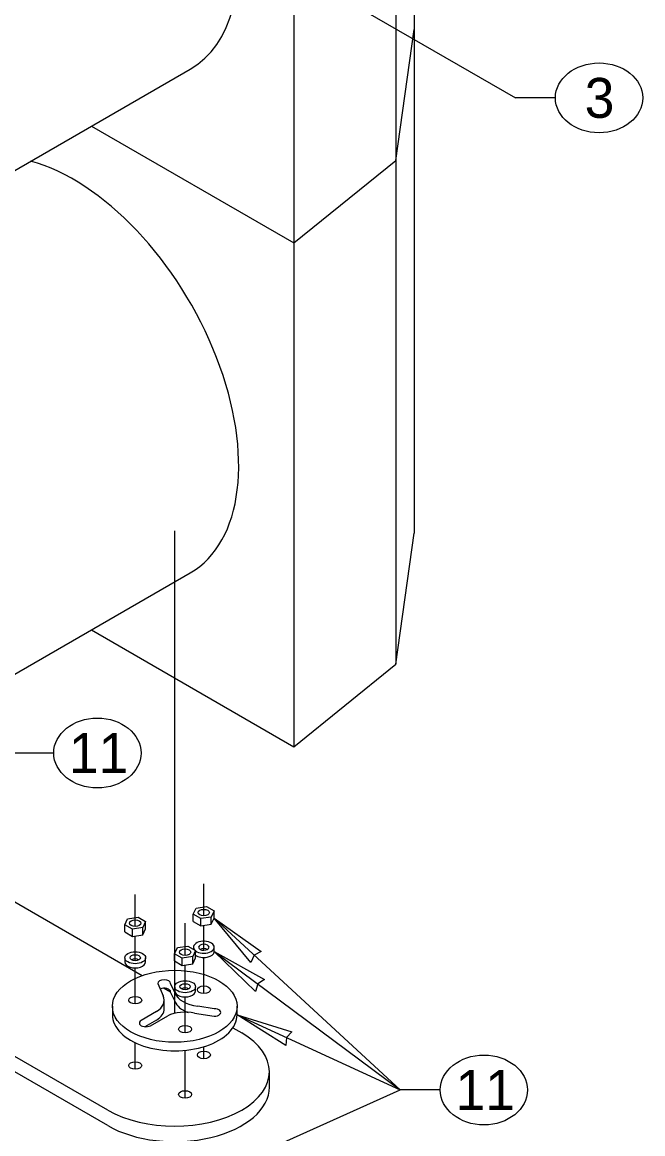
# Model space of a CAD drawing. Extents: x 99862 to 104211, y 98939 to 105076.
# Drawn here: x 101103.8 to 101352.5, y 103287.2 to 103732.8 of the extents above; entities that cross this region are included whole.
import ezdxf

# ---------------------------------------------------------------- set-up
doc = ezdxf.new("R2010")
doc.units = 0
for name, color, linetype in [('Level 11', 7, 'Continuous'), ('Level 12', 7, 'Continuous'), ('Level 15', 7, 'Continuous'), ('Level 19', 7, 'Continuous'), ('Level 20', 7, 'Continuous'), ('Level 21', 7, 'Continuous'), ('Level 26', 7, 'Continuous'), ('Level 8', 7, 'Continuous')]:
    doc.layers.add(name, color=color, linetype=linetype)

msp = doc.modelspace()

# ---------------------------------------------------------------- linework, layer by layer
at = {"layer": 'Level 11'}
for p, q in [((101172.31, 103375.22), (101173.43, 103377.64)), ((101173.43, 103377.64), (101177.61, 103378.28)), ((101177.61, 103378.28), (101180.67, 103376.52)), ((101144.87, 103371.02), (101145.99, 103373.43)), ((101145.99, 103373.43), (101150.17, 103374.08)), ((101150.17, 103374.08), (101153.23, 103372.31)), ((101172.31, 103372.31), (101172.31, 103375.22)), ((101175.37, 103373.45), (101172.31, 103375.22)), ((101179.55, 103374.1), (101175.37, 103373.45)), ((101175.37, 103370.54), (101175.37, 103373.45)), ((101180.67, 103376.52), (101179.55, 103374.1)), ((101179.55, 103371.19), (101179.55, 103374.1)), ((101179.55, 103371.19), (101180.67, 103373.61)), ((101180.67, 103373.61), (101180.67, 103376.52)), ((101144.87, 103368.11), (101144.87, 103371.02)), ((101147.93, 103369.25), (101144.87, 103371.02)), ((101144.87, 103368.11), (101147.93, 103366.34)), ((101152.11, 103369.9), (101147.93, 103369.25)), ((101147.93, 103366.34), (101147.93, 103369.25)), ((101153.23, 103372.31), (101152.11, 103369.9)), ((101152.11, 103366.99), (101152.11, 103369.9)), ((101152.11, 103366.99), (101153.23, 103369.4)), ((101153.23, 103369.4), (101153.23, 103372.31)), ((101172.31, 103372.31), (101175.37, 103370.54)), ((101175.37, 103370.54), (101179.55, 103371.19)), ((101147.93, 103366.34), (101152.11, 103366.99)), ((101164.86, 103359.4), (101165.98, 103361.82)), ((101164.86, 103356.5), (101164.86, 103359.4)), ((101167.92, 103357.64), (101164.86, 103359.4)), ((101165.98, 103361.82), (101170.16, 103362.47)), ((101170.16, 103362.47), (101173.22, 103360.7)), ((101173.22, 103360.7), (101172.1, 103358.28)), ((101172.4, 103361.98), (101172.4, 103361.18)), ((101173.22, 103357.79), (101173.22, 103360.7)), ((101180.73, 103360.28), (101180.73, 103361.98)), ((101144.89, 103357.78), (101144.89, 103356.08)), ((101153.22, 103356.08), (101153.22, 103357.78)), ((101164.86, 103356.5), (101167.92, 103354.73)), ((101172.1, 103358.28), (101167.92, 103357.64)), ((101167.92, 103354.73), (101167.92, 103357.64)), ((101167.92, 103354.73), (101172.1, 103355.37)), ((101172.1, 103355.37), (101172.1, 103358.28)), ((101172.1, 103355.37), (101173.22, 103357.79)), ((101158.05, 103347.44), (101160.27, 103342.48)), ((101165.03, 103343.63), (101163.25, 103347.44)), ((101164.87, 103346.17), (101164.87, 103344.47)), ((101173.21, 103344.47), (101173.21, 103346.17)), ((101165.03, 103340.22), (101163.25, 103344.04)), ((101139.89, 103338.3), (101139.89, 103334.89)), ((101160.66, 103337.34), (101160.66, 103340.75)), ((101180.74, 103337.35), (101174.13, 103338.37)), ((101189.89, 103334.89), (101189.89, 103338.3)), ((101157.58, 103336.2), (101151.46, 103332.66)), ((101157.58, 103332.8), (101152.93, 103330.11)), ((101155.14, 103330.54), (101162.06, 103334.53)), ((101172.82, 103335.57), (101180.74, 103334.34))]:
    msp.add_line(p, q, dxfattribs=at)
for centre, major_axis in [((101176.49, 103375.87), (2.27, 0)), ((101149.05, 103371.66), (2.27, 0)), ((101149.05, 103357.78), (-4.17, 0)), ((101169.04, 103360.05), (2.27, 0)), ((101149.05, 103357.78), (-2.08, 0)), ((101164.89, 103338.3), (-25, 0)), ((101169.04, 103346.17), (-4.17, 0)), ((101169.04, 103346.17), (-2.08, 0)), ((101176.56, 103344.95), (-2.6, 0)), ((101149.05, 103340.75), (-2.6, 0)), ((101169.04, 103329.13), (-2.6, 0))]:
    msp.add_ellipse(centre, major_axis=major_axis, ratio=0.57735, dxfattribs=at)
for centre, major_axis, start_param, end_param in [((101176.56, 103361.98), (-4.17, 0), 0.640708, 6.732556), ((101176.56, 103360.28), (-4.17, 0), 0.640708, 3.141593), ((101176.56, 103361.98), (-2.08, 0), 0.014662, 6.296698), ((101176.56, 103360.28), (-2.08, 0), 3.926991, 5.497787), ((101149.05, 103356.08), (-4.17, 0), 0, 3.141593), ((101149.05, 103356.08), (-2.08, 0), 3.926991, 5.497787), ((101160.65, 103347.44), (-2.6, 0), 3.141593, 6.283185), ((101160.65, 103344.04), (-2.6, 0), 3.141593, 5.379094), ((101169.04, 103344.47), (-2.08, 0), 3.926991, 5.497787), ((101149.05, 103340.75), (-11.61, 0), 2.396309, 3.403392), ((101169.04, 103344.47), (-4.17, 0), 6.283185, 9.424778), ((101176.49, 103344.99), (-11.71, 0), 0.203445, 1.367352), ((101149.05, 103337.34), (-11.61, 0), 2.396309, 3.141593), ((101176.49, 103341.59), (-11.71, 0), 0.203445, 1.005854), ((101180.74, 103335.85), (-2.6, 0), 1.570796, 4.712389), ((101164.89, 103334.89), (-25, 0), 6.283185, 9.424778), ((101153.3, 103331.6), (-2.6, 0), 5.497787, 8.63938), ((101169.14, 103329.15), (-11.71, 0), 4.392235, 5.361438)]:
    msp.add_ellipse(centre, major_axis=major_axis, ratio=0.57735, start_param=start_param, end_param=end_param, dxfattribs=at)
at = {"layer": 'Level 12'}
msp.add_line((101138.06, 103296.65), (100913.51, 103426.3), dxfattribs=at)
at = {"layer": 'Level 15'}
for p, q in [((101183.01, 103770.87), (101301.48, 103702.47)), ((101317.48, 103702.47), (101301.48, 103702.47)), ((101164.89, 103335.45), (101164.89, 103528.85)), ((101116.39, 103439.85), (101100.39, 103439.85)), ((101176.49, 103374.56), (101176.49, 103387.4)), ((101149.05, 103370.35), (101149.05, 103383.19)), ((101180.67, 103373.61), (101255.3, 103304.76)), ((101169.04, 103358.74), (101169.04, 103371.58)), ((101176.49, 103360.78), (101176.49, 103370.72)), ((101149.05, 103356.57), (101149.05, 103366.51)), ((101180.73, 103360.28), (101255.3, 103304.76)), ((101169.04, 103344.96), (101169.04, 103354.9)), ((101176.49, 103343.45), (101176.49, 103357.88)), ((101149.05, 103339.24), (101149.05, 103353.67)), ((101169.04, 103327.63), (101169.04, 103342.06)), ((101189.89, 103334.89), (101255.3, 103304.76)), ((101149.05, 103313.09), (101149.05, 103323.73)), ((101169.04, 103301.48), (101169.04, 103320.66)), ((101176.56, 103317.29), (101176.56, 103322.13)), ((101178.58, 103270.45), (101255.3, 103304.76)), ((101271.3, 103304.76), (101255.3, 103304.76))]:
    msp.add_line(p, q, dxfattribs=at)
for points in [[(101180.67, 103373.61), (101199.48, 103360.32), (101196.68, 103358.84), (101195.43, 103355.93)], [(101180.73, 103360.28), (101200.82, 103349.04), (101198.19, 103347.28), (101197.26, 103344.25)], [(101189.89, 103334.89), (101211.88, 103328.05), (101209.67, 103325.78), (101209.38, 103322.63)]]:
    msp.add_lwpolyline(points, close=True, dxfattribs=at)
at = {"layer": 'Level 19'}
for p, q in [((101253.57, 103677.43), (101260.91, 103729.92)), ((101212.62, 103644.32), (101253.57, 103677.43)), ((101253.57, 103475.48), (101260.91, 103527.98)), ((101212.62, 103442.37), (101253.57, 103475.48))]:
    msp.add_line(p, q, dxfattribs=at)
at = {"layer": 'Level 20'}
for centre in [(101334.98, 103702.47), (101133.89, 103439.85), (101288.8, 103304.76)]:
    msp.add_ellipse(centre, major_axis=(-17.5, 0), ratio=0.8, dxfattribs=at)
at = {"layer": 'Level 21'}
for p, q in [((101138.06, 103290.46), (100913.51, 103420.1)), ((101049.05, 103410), (101151.9, 103350.63)), ((101160.71, 103345.54), (101163.25, 103344.07)), ((101188.2, 103329.67), (101191.73, 103327.63))]:
    msp.add_line(p, q, dxfattribs=at)
for centre, end_param in [((101164.89, 103312.14), 7.068583), ((101164.89, 103305.95), 6.283185)]:
    msp.add_ellipse(centre, major_axis=(37.94, 0), ratio=0.57735, start_param=3.926991, end_param=end_param, dxfattribs=at)
for centre in [(101176.56, 103318.8), (101149.05, 103314.59), (101169.04, 103302.98)]:
    msp.add_ellipse(centre, major_axis=(-2.6, 0), ratio=0.57735, dxfattribs=at)
at = {"layer": 'Level 26'}
for p, q in [((101260.91, 103916.53), (101260.91, 103729.92)), ((101253.57, 103869.91), (101253.57, 103677.43)), ((101212.62, 103846.27), (101212.62, 103644.32)), ((101260.91, 103729.92), (101260.91, 103527.98)), ((101065.04, 103652.81), (101171.1, 103714.04)), ((101131.47, 103691.17), (101212.62, 103644.32)), ((101131.47, 103691.17), (101212.62, 103644.32)), ((101253.57, 103677.43), (101253.57, 103475.48)), ((101212.62, 103644.32), (101212.62, 103442.37)), ((101065.04, 103450.86), (101171.1, 103512.1)), ((101131.47, 103489.22), (101212.62, 103442.37))]:
    msp.add_line(p, q, dxfattribs=at)
for centre, end_param in [((101124.23, 103795.23), 3.141593), ((101124.23, 103593.29), 2.616954)]:
    msp.add_ellipse(centre, major_axis=(46.88, -81.19), ratio=0.57735, start_param=0, end_param=end_param, dxfattribs=at)
at = {"layer": 'Level 8'}
msp.add_line((101202.84, 103305.95), (101202.84, 103312.14), dxfattribs=at)

# ---------------------------------------------------------------- texts
at = {"layer": 'Level 20'}
for s, p in [('3', (101329.2, 103694.47)), ('11', (101122.51, 103431.85)), ('11', (101277.41, 103296.76))]:
    msp.add_text(s, height=16, dxfattribs=at).set_placement(p)

doc.saveas('drawing.dxf')
